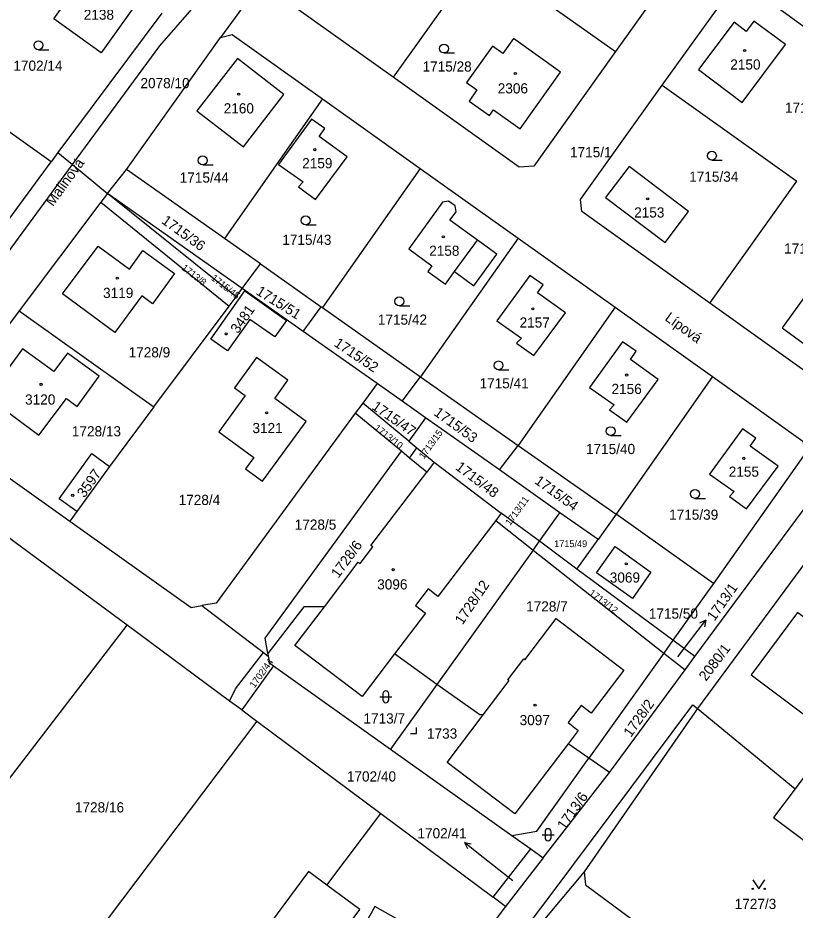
# Model space of a CAD drawing. Extents: x -679220 to -673243, y -1075091 to -1066557.
# Drawn here: x -677014 to -676884, y -1072084.9 to -1071935.7 of the extents above; entities that cross this region are included whole.
import ezdxf

# ---------------------------------------------------------------- set-up
doc = ezdxf.new("R2010")
doc.units = 0
for name, color, linetype in [('Hranice parcel', 7, 'Continuous'), ('Parcelní čísla', 7, 'Continuous'), ('Pop  PČ popisy', 7, 'Continuous'), ('Vnitřní kresba', 7, 'Continuous'), ('Značky budov', 7, 'Continuous'), ('Značky kultur', 7, 'Continuous')]:
    doc.layers.add(name, color=color, linetype=linetype)

msp = doc.modelspace()

# ---------------------------------------------------------------- linework, layer by layer
at = {"layer": 'Hranice parcel'}
for p, q in [((-676901.29, -1071923.42), (-676914.04, -1071941.35)), ((-676936.67, -1071925.2), (-676951.19, -1071945.63)), ((-676936.67, -1071925.2), (-676914.04, -1071941.35)), ((-676972.46, -1071928.53), (-676980.07, -1071938.97)), ((-676906.21, -1071946.96), (-676893.51, -1071929.18)), ((-676893.51, -1071929.18), (-676871.16, -1071945.4)), ((-676989.9, -1071934.91), (-677007.25, -1071958.24)), ((-676995.79, -1071961.08), (-676980.07, -1071938.97)), ((-677008.37, -1071959.75), (-677027, -1071946.58)), ((-676906.21, -1071946.96), (-676883.7, -1071963)), ((-676963.02, -1071949.25), (-676979.39, -1071972.61)), ((-676963.02, -1071949.25), (-676946.71, -1071960.86)), ((-677007.25, -1071958.24), (-677008.37, -1071959.75)), ((-677007.25, -1071958.24), (-677004.82, -1071960.24)), ((-677038.35, -1072005.77), (-677004.82, -1071960.24)), ((-677004.82, -1071960.24), (-676998.96, -1071965.06)), ((-676946.71, -1071960.86), (-676963.04, -1071984.14)), ((-676946.71, -1071960.86), (-676930.33, -1071972.54)), ((-676998.96, -1071965.06), (-676995.79, -1071961.08)), ((-676979.39, -1071972.61), (-676995.79, -1071961.08)), ((-676898.24, -1071983.39), (-676883.7, -1071963)), ((-676998.96, -1071965.06), (-677000.06, -1071966.52)), ((-676976.46, -1071980.95), (-676998.96, -1071965.06)), ((-676977.47, -1071982.31), (-676998.96, -1071965.06)), ((-677000.06, -1071966.52), (-677013.72, -1071984.7)), ((-677000.06, -1071966.52), (-676978.64, -1071983.88)), ((-676973.4, -1071976.84), (-676979.39, -1071972.61)), ((-676930.33, -1071972.54), (-676946.62, -1071995.69)), ((-676930.33, -1071972.54), (-676914.09, -1071984.09)), ((-676976.46, -1071980.95), (-676973.4, -1071976.84)), ((-676973.4, -1071976.84), (-676963.24, -1071983.99)), ((-676977.47, -1071982.31), (-676976.46, -1071980.95)), ((-676966.23, -1071988.15), (-676976.46, -1071980.95)), ((-676978.64, -1071983.88), (-676977.47, -1071982.31)), ((-677013.72, -1071984.7), (-676991.21, -1072000.73)), ((-676991.21, -1072000.73), (-676978.64, -1071983.88)), ((-676966.23, -1071988.15), (-676963.24, -1071983.99)), ((-676963.24, -1071983.99), (-676963.04, -1071984.14)), ((-676963.04, -1071984.14), (-676946.62, -1071995.69)), ((-676914.09, -1071984.09), (-676930.32, -1072007.19)), ((-676914.09, -1071984.09), (-676897.82, -1071995.66)), ((-676953.9, -1071996.85), (-676966.23, -1071988.15)), ((-676949.7, -1071999.8), (-676946.62, -1071995.69)), ((-676946.62, -1071995.69), (-676930.32, -1072007.19)), ((-676897.82, -1071995.66), (-676913.91, -1072018.68)), ((-676953.9, -1071996.85), (-676956.29, -1072000.12)), ((-676949.7, -1071999.8), (-676953.9, -1071996.85)), ((-676991.21, -1072000.73), (-676998.63, -1072010.68)), ((-676956.29, -1072000.12), (-676957.53, -1072001.81)), ((-676948.59, -1072006.45), (-676956.29, -1072000.12)), ((-676945.77, -1072002.57), (-676949.7, -1071999.8)), ((-676949.83, -1072008.14), (-676957.53, -1072001.81)), ((-676945.77, -1072002.57), (-676948.59, -1072006.45)), ((-676933.45, -1072011.27), (-676945.77, -1072002.57)), ((-676948.59, -1072006.45), (-676947.23, -1072007.57)), ((-676948.45, -1072009.28), (-676949.83, -1072008.14)), ((-676948.45, -1072009.28), (-676947.23, -1072007.57)), ((-676947.23, -1072007.57), (-676944.34, -1072009.96)), ((-676933.45, -1072011.27), (-676930.32, -1072007.19)), ((-676930.32, -1072007.19), (-676913.91, -1072018.68)), ((-676945.6, -1072011.62), (-676948.45, -1072009.28)), ((-676944.34, -1072009.96), (-676945.6, -1072011.62)), ((-676944.34, -1072009.96), (-676933.12, -1072018.49)), ((-676998.63, -1072010.68), (-677004.08, -1072018.21)), ((-676923.36, -1072018.44), (-676933.45, -1072011.27)), ((-676900.74, -1072042.46), (-676877.7, -1072011.25)), ((-676873.46, -1072014.72), (-676900.33, -1072051.15)), ((-677004.08, -1072018.21), (-677005.26, -1072019.82)), ((-676933.12, -1072018.49), (-676934.06, -1072019.73)), ((-676926.76, -1072023.2), (-676933.12, -1072018.49)), ((-676926.76, -1072023.2), (-676923.36, -1072018.44)), ((-676916.94, -1072022.92), (-676923.36, -1072018.44)), ((-676913.91, -1072018.68), (-676916.94, -1072022.92)), ((-676897.67, -1072030.26), (-676913.91, -1072018.68)), ((-676934.06, -1072019.73), (-676927.81, -1072024.66)), ((-676995.7, -1072037.23), (-677017.03, -1072021.51)), ((-676927.81, -1072024.66), (-676926.76, -1072023.2)), ((-676920.47, -1072027.86), (-676926.76, -1072023.2)), ((-676920.47, -1072027.86), (-676916.94, -1072022.92)), ((-676927.81, -1072024.66), (-676943.88, -1072047.12)), ((-676927.81, -1072024.66), (-676905.97, -1072041.9)), ((-676904.42, -1072039.73), (-676920.47, -1072027.86)), ((-676897.67, -1072030.26), (-676904.42, -1072039.73)), ((-676983.19, -1072033.95), (-676972.88, -1072041.79)), ((-677028.68, -1072080.19), (-676995.7, -1072037.23)), ((-676978.55, -1072049.91), (-676995.7, -1072037.23)), ((-676904.42, -1072039.73), (-676905.97, -1072041.9)), ((-676900.74, -1072042.46), (-676904.42, -1072039.73)), ((-676972.88, -1072041.79), (-676972.1, -1072042.38)), ((-676972.16, -1072041.94), (-676972.1, -1072042.38)), ((-676943.88, -1072047.12), (-676950.99, -1072042.03)), ((-676905.97, -1072041.9), (-676918.48, -1072059.45)), ((-676905.97, -1072041.9), (-676902.4, -1072044.71)), ((-676902.4, -1072044.71), (-676900.74, -1072042.46)), ((-676971.22, -1072044.03), (-676976.51, -1072051.39)), ((-676971.22, -1072044.03), (-676951.64, -1072057.95)), ((-676943.88, -1072047.12), (-676951.64, -1072057.95)), ((-676976.51, -1072051.39), (-676978.55, -1072049.91)), ((-676976.51, -1072051.39), (-676973.98, -1072053.28)), ((-676900.33, -1072051.15), (-676919.29, -1072078.44)), ((-676900.33, -1072051.15), (-676884, -1072064.55)), ((-676973.98, -1072053.28), (-676953.27, -1072068.7)), ((-676918.48, -1072059.45), (-676921.97, -1072057.07)), ((-676951.64, -1072057.95), (-676931.36, -1072072.37)), ((-676915.01, -1072061.82), (-676918.48, -1072059.45)), ((-676926.11, -1072076.11), (-676915.01, -1072061.82)), ((-676962.32, -1072080.65), (-676953.27, -1072068.7)), ((-676953.27, -1072068.7), (-676934.47, -1072082.69)), ((-676931.36, -1072072.37), (-676928.2, -1072074.62)), ((-676934.47, -1072082.69), (-676928.2, -1072074.62)), ((-676928.2, -1072074.62), (-676926.11, -1072076.11)), ((-676926.11, -1072076.11), (-676932.42, -1072084.22)), ((-676919.29, -1072078.44), (-676927.29, -1072088.05)), ((-676932.42, -1072084.22), (-676934.47, -1072082.69)), ((-676932.42, -1072084.22), (-676965.77, -1072128.57))]:
    msp.add_line(p, q, dxfattribs=at)
for points in [[(-677004.82, -1071960.24), (-676990.19, -1071940.38), (-676962.75, -1071908.83), (-676942.14, -1071882.34), (-676915.32, -1071846.3), (-676903, -1071827.69)], [(-677000.04, -1071941.54), (-677007.96, -1071935.89), (-677002.6, -1071928.37), (-677001.38, -1071929.24), (-677000.07, -1071927.33), (-676993.33, -1071932.13), (-677000.04, -1071941.54)], [(-676951.19, -1071945.63), (-676972.45, -1071930.47), (-676972.46, -1071928.53)], [(-676892.16, -1071937.98), (-676894.19, -1071936.45), (-676900.14, -1071944.35), (-676892.87, -1071949.83), (-676885.6, -1071940.18), (-676890.9, -1071936.24), (-676892.16, -1071937.98)], [(-676980.07, -1071938.97), (-676978.14, -1071938.48), (-676963.02, -1071949.25)], [(-676938.48, -1071949.61), (-676935.11, -1071952.02), (-676934.42, -1071951.06), (-676929.97, -1071954.25), (-676923.2, -1071944.8), (-676931.08, -1071939.16), (-676932.85, -1071941.66), (-676934.58, -1071940.42), (-676938.94, -1071946.51), (-676937.21, -1071947.75), (-676938.48, -1071949.61)], [(-676914.04, -1071941.35), (-676927.67, -1071960.51), (-676930.16, -1071960.64), (-676951.19, -1071945.63)], [(-676977.25, -1071942.49), (-676984.02, -1071951.26), (-676976.24, -1071957.27), (-676969.47, -1071948.5), (-676977.25, -1071942.49)], [(-676898.24, -1071983.39), (-676919.64, -1071968.09), (-676919.87, -1071966.08), (-676906.21, -1071946.96)], [(-676958.9, -1071958.91), (-676963.56, -1071955.56), (-676962.61, -1071954.2), (-676964.84, -1071952.64), (-676970.36, -1071960.24), (-676966.25, -1071963.14), (-676967.05, -1071963.96), (-676964.17, -1071966.06), (-676958.9, -1071958.91)], [(-677063.84, -1071978.51), (-677036.99, -1071997.4), (-677035.86, -1071997.1), (-677008.37, -1071959.75)], [(-676911.75, -1071960.55), (-676915.69, -1071965.74), (-676905.75, -1071973.26), (-676901.84, -1071968.09), (-676911.75, -1071960.55)], [(-676944.73, -1071977.13), (-676945.43, -1071978.09), (-676942.48, -1071980.24), (-676940.94, -1071978.13), (-676937.71, -1071980.48), (-676933.86, -1071975.21), (-676937.09, -1071972.88), (-676941.72, -1071969.55), (-676940.69, -1071968.11), (-676940.83, -1071967.14), (-676941.97, -1071966.35), (-676942.95, -1071966.49), (-676948.6, -1071974.31), (-676944.73, -1071977.13)], [(-677000.55, -1071973.86), (-676995.3, -1071977.69), (-676993.03, -1071974.58), (-676987.75, -1071978.44), (-676991.42, -1071983.5), (-676993.23, -1071982.17), (-676997.73, -1071988.29), (-677006.47, -1071981.86), (-677000.55, -1071973.86)], [(-676926.12, -1071980.31), (-676928.35, -1071978.75), (-676933.87, -1071986.35), (-676929.77, -1071989.25), (-676930.56, -1071990.07), (-676927.68, -1071992.17), (-676922.41, -1071985.02), (-676927.07, -1071981.67), (-676926.12, -1071980.31)], [(-676877.28, -1071993.98), (-676870.29, -1071984.34), (-676879.2, -1071977.88), (-676886.19, -1071987.51), (-676877.28, -1071993.98)], [(-676861.04, -1071979.15), (-676874.99, -1071998.27), (-676877.55, -1071998.21), (-676898.24, -1071983.39)], [(-676981.68, -1071989.39), (-676976.02, -1071981.35), (-676969.05, -1071986.32), (-676971, -1071989.04), (-676975.18, -1071986.11), (-676978.89, -1071991.38), (-676981.68, -1071989.39)], [(-677013.72, -1071984.7), (-677026.18, -1072001.27), (-677025.53, -1072005.41), (-677005.26, -1072019.82)], [(-676906.89, -1071996.14), (-676911.55, -1071992.8), (-676910.6, -1071991.43), (-676912.84, -1071989.87), (-676918.36, -1071997.48), (-676914.25, -1072000.37), (-676915.05, -1072001.2), (-676912.16, -1072003.3), (-676906.89, -1071996.14)], [(-677005.66, -1071991.74), (-677007.93, -1071994.84), (-677013.18, -1071991.02), (-677019.07, -1071999.03), (-677010.45, -1072005.45), (-677005.84, -1071999.31), (-677004.04, -1072000.66), (-677000.38, -1071995.59), (-677005.66, -1071991.74)], [(-676971, -1071999.35), (-676968.79, -1071996.29), (-676974.06, -1071992.48), (-676977.72, -1071997.55), (-676975.97, -1071998.82), (-676980.37, -1072004.9), (-676974.51, -1072009.19), (-676975.88, -1072011.06), (-676973.03, -1072013.17), (-676965.73, -1072003.16), (-676971, -1071999.35)], [(-676897.82, -1071995.66), (-676882.69, -1072006.44), (-676882.34, -1072008.54), (-676897.67, -1072030.26)], [(-676957.53, -1072001.81), (-676980.77, -1072033.56), (-676983.19, -1072033.95)], [(-676891.5, -1072007.3), (-676890.55, -1072005.94), (-676892.79, -1072004.38), (-676898.31, -1072011.98), (-676894.2, -1072014.88), (-676894.99, -1072015.7), (-676892.11, -1072017.8), (-676886.84, -1072010.65), (-676891.5, -1072007.3)], [(-677004.08, -1072018.21), (-677007.03, -1072016.08), (-677001.58, -1072008.55), (-676998.63, -1072010.68)], [(-676972.16, -1072041.94), (-676972.59, -1072039.38), (-676949.83, -1072008.14)], [(-676962.71, -1072034.15), (-676957.03, -1072026.69), (-676956.73, -1072026.91), (-676954.62, -1072024.13), (-676954.93, -1072023.88), (-676945.6, -1072011.62)], [(-677005.26, -1072019.82), (-676984.99, -1072034.24), (-676983.19, -1072033.95)], [(-676934.06, -1072019.73), (-676943.72, -1072032.43), (-676945.37, -1072031.15), (-676947.49, -1072033.94), (-676945.82, -1072035.21), (-676950.99, -1072042.03)], [(-676917.21, -1072028.45), (-676914.09, -1072024.08), (-676908.14, -1072028.37), (-676911.21, -1072032.74), (-676917.21, -1072028.45)], [(-676962.71, -1072034.15), (-676966.11, -1072034.14), (-676972.16, -1072041.94)], [(-676950.99, -1072042.03), (-676956.41, -1072049.16), (-676967.62, -1072040.6), (-676962.71, -1072034.15)], [(-676868.02, -1072077.66), (-676867.08, -1072076.45), (-676872.09, -1072072.31), (-676868.03, -1072066.91), (-676866.12, -1072068.42), (-676863.83, -1072065.54), (-676867.87, -1072061.91), (-676862.44, -1072054.78), (-676858.43, -1072057.77), (-676851.76, -1072049.4), (-676847.29, -1072052.86), (-676843.34, -1072047.64), (-676857.56, -1072036.75), (-676866.88, -1072047.56), (-676883.62, -1072035.08), (-676891.33, -1072045.54), (-676877.52, -1072055.87), (-676884, -1072064.55)], [(-676936.15, -1072052.22), (-676931.81, -1072046.49), (-676932.01, -1072046.34), (-676929.38, -1072042.87), (-676929.17, -1072043.03), (-676923.94, -1072036.13), (-676912.63, -1072044.75), (-676918.09, -1072051.93), (-676919.78, -1072050.64), (-676921.96, -1072053.51), (-676920.25, -1072054.81), (-676921.97, -1072057.07)], [(-676978.55, -1072049.91), (-676977.55, -1072047.85), (-676972.88, -1072041.79)], [(-676972.1, -1072042.38), (-676971.9, -1072043.53), (-676971.22, -1072044.03)], [(-676915.01, -1072061.82), (-676914.7, -1072061.42), (-676902.4, -1072044.71)], [(-676936.15, -1072052.22), (-676936.74, -1072052.23), (-676943.88, -1072047.12)], [(-677003.56, -1072188.05), (-676937.07, -1072098.47), (-676924.77, -1072082.25), (-676901.08, -1072050.53), (-676900.33, -1072051.15)], [(-676973.98, -1072053.28), (-677000.89, -1072088.91), (-677006.95, -1072096.23)], [(-676921.97, -1072057.07), (-676930.86, -1072068.74), (-676942.16, -1072060.15), (-676936.15, -1072052.22)], [(-676931.36, -1072072.37), (-676927.2, -1072071.67), (-676918.48, -1072059.45)], [(-676884, -1072064.55), (-676887.59, -1072069.36), (-676871.15, -1072081.68), (-676868.02, -1072077.66)], [(-676962.32, -1072080.65), (-676965.37, -1072078.39), (-676971.7, -1072086.99), (-676968.77, -1072089.16)], [(-676919.29, -1072078.44), (-676919.07, -1072080.61), (-676880.11, -1072109.47), (-676878.47, -1072110.68)], [(-676968.77, -1072089.16), (-676963.12, -1072093.36), (-676960.03, -1072089.15), (-676957.88, -1072090.71), (-676961.29, -1072096.87), (-676956.26, -1072099.62), (-676957.84, -1072102.51), (-676957.52, -1072102.7), (-676948.9, -1072087.27), (-676954.27, -1072084.27), (-676956.41, -1072088.09), (-676958.21, -1072086.72), (-676956.77, -1072084.77), (-676962.32, -1072080.65)]]:
    msp.add_lwpolyline(points, dxfattribs=at)
at = {"layer": 'Pop  PČ popisy'}
for p, q in [((-676900.76, -1072038.79), (-676898.95, -1072036.39)), ((-676898.95, -1072036.39), (-676899.96, -1072036.89)), ((-676898.95, -1072036.39), (-676899.16, -1072037.49)), ((-676903.61, -1072042.52), (-676900.76, -1072038.79)), ((-676936.92, -1072075.43), (-676939.25, -1072073.54)), ((-676939.25, -1072073.54), (-676938.16, -1072073.78)), ((-676939.25, -1072073.54), (-676938.79, -1072074.56)), ((-676931.22, -1072079.98), (-676936.92, -1072075.43))]:
    msp.add_line(p, q, dxfattribs=at)
at = {"layer": 'Vnitřní kresba'}
msp.add_line((-676940.94, -1071978.13), (-676937.09, -1071972.88), dxfattribs=at)
at = {"layer": 'Značky budov'}
for centre in [(-676892.44, -1071941.17), (-676930.78, -1071945.01), (-676977.04, -1071948.47), (-676964.31, -1071957.74), (-676908.65, -1071965.96), (-676942.82, -1071972.32), (-676997.32, -1071979.22), (-676927.85, -1071984.34), (-676979.13, -1071988.54), (-676912.17, -1071995.41), (-677010.07, -1071996.96), (-676972.36, -1072001.73), (-676892.58, -1072009.33), (-677004.78, -1072015.51), (-676951.2, -1072027.94), (-676912.23, -1072026.98), (-676927.48, -1072050.58)]:
    msp.add_circle(centre, 0.175, dxfattribs=at)
at = {"layer": 'Značky kultur'}
for p, q in [((-677010.5, -1071941.03), (-677008.75, -1071941.03)), ((-676942.71, -1071941.58), (-676940.96, -1071941.58)), ((-676983.04, -1071960.29), (-676981.29, -1071960.29)), ((-676897.92, -1071959.51), (-676896.17, -1071959.51)), ((-676965.83, -1071970.32), (-676964.08, -1071970.32)), ((-676950.17, -1071983.85), (-676948.42, -1071983.85)), ((-676933.59, -1071994.56), (-676931.84, -1071994.56)), ((-676914.84, -1072005.54), (-676913.09, -1072005.54)), ((-676900.74, -1072016.02), (-676898.99, -1072016.02)), ((-676952.93, -1072048.69), (-676952.93, -1072049.69)), ((-676951.93, -1072049.69), (-676951.93, -1072048.69)), ((-676953.43, -1072049.19), (-676951.43, -1072049.19)), ((-676947.3, -1072055.33), (-676947.3, -1072054.33)), ((-676948.3, -1072055.33), (-676947.3, -1072055.33)), ((-676926.31, -1072072.24), (-676924.31, -1072072.24)), ((-676925.81, -1072071.74), (-676925.81, -1072072.74)), ((-676924.81, -1072072.74), (-676924.81, -1072071.74))]:
    msp.add_line(p, q, dxfattribs=at)
msp.add_lwpolyline([(-676891.09, -1072079.79), (-676890.09, -1072081.29), (-676889.09, -1072079.79)], dxfattribs=at)
for centre, radius in [((-677010.5, -1071940.28), 0.75), ((-676942.71, -1071940.83), 0.75), ((-676983.04, -1071959.54), 0.75), ((-676897.92, -1071958.76), 0.75), ((-676965.83, -1071969.57), 0.75), ((-676950.17, -1071983.1), 0.75), ((-676933.59, -1071993.81), 0.75), ((-676914.84, -1072004.79), 0.75), ((-676900.74, -1072015.27), 0.75), ((-676891.09, -1072081.29), 0.1), ((-676889.09, -1072081.29), 0.1)]:
    msp.add_circle(centre, radius, dxfattribs=at)
for centre, start, end in [((-676952.43, -1072048.69), 0, 180), ((-676952.43, -1072049.69), 180, 359.9879), ((-676925.31, -1072071.74), 0, 180), ((-676925.31, -1072072.74), 180, 359.9879)]:
    msp.add_arc(centre, 0.5, start, end, dxfattribs=at)

# ---------------------------------------------------------------- texts
at = {"layer": 'Parcelní čísla'}
for s, height, p in [('2138', 1.7, (-677002.93, -1071936.02)), ('1702/14', 1.7, (-677014.7, -1071944.55)), ('1715/28', 1.7, (-676946.29, -1071944.69)), ('2150', 1.7, (-676894.84, -1071944.35)), ('2078/10', 1.7, (-676993.45, -1071947.46)), ('2306', 1.7, (-676933.72, -1071948.34)), ('2160', 1.7, (-676979.54, -1071951.68)), ('1715/31', 1.7, (-676885.7, -1071951.57)), ('1715/1', 1.7, (-676921.64, -1071959.01)), ('2159', 1.7, (-676966.41, -1071960.85)), ('1715/44', 1.7, (-676986.89, -1071963.25)), ('1715/34', 1.7, (-676901.71, -1071963.1)), ('2153', 1.7, (-676910.91, -1071969.08)), ('1715/43', 1.7, (-676969.74, -1071973.65)), ('2158', 1.7, (-676945.18, -1071975.48)), ('1715/35', 1.7, (-676885.84, -1071975.11)), ('3119', 1.7, (-676999.7, -1071982.53)), ('1715/42', 1.7, (-676953.76, -1071987)), ('2157', 1.7, (-676930.07, -1071987.48)), ('1728/9', 1.7, (-676995.43, -1071992.46)), ('1715/41', 1.7, (-676936.76, -1071997.64)), ('2156', 1.7, (-676914.7, -1071998.58)), ('3120', 1.7, (-677012.74, -1072000.35)), ('1728/13', 1.7, (-677004.92, -1072005.66)), ('3121', 1.7, (-676974.73, -1072005.12)), ('1715/40', 1.7, (-676918.97, -1072008.62)), ('2155', 1.7, (-676895.1, -1072012.41)), ('1728/4', 1.7, (-676987.07, -1072017.13)), ('1715/39', 1.7, (-676905.07, -1072019.6)), ('1728/5', 1.7, (-676967.66, -1072021.26)), ('1715/49', 1.14, (-676924.28, -1072024.18)), ('3096', 1.7, (-676953.87, -1072031.25)), ('3069', 1.7, (-676914.99, -1072030.1)), ('1728/7', 1.7, (-676928.97, -1072034.93)), ('1715/50', 1.7, (-676908.46, -1072036.13)), ('1713/7', 1.7, (-676956.17, -1072053.66)), ('3097', 1.7, (-676930.06, -1072053.93)), ('1733', 1.7, (-676945.55, -1072056.18)), ('1702/40', 1.7, (-676958.94, -1072063.35)), ('1728/16', 1.7, (-677004.41, -1072068.52)), ('1702/41', 1.7, (-676947.14, -1072072.85)), ('1727/3', 1.7, (-676894.11, -1072084.66))]:
    msp.add_text(s, height=height, dxfattribs=at).set_placement(p)
for s, height, rotation, p in [('1715/36', 1.7, 324, (-676990.05, -1071969.93)), ('1713/8', 1.14, 322, (-676986.67, -1071977.69)), ('1715/45', 1.14, 322, (-676981.73, -1071979.4)), ('1715/51', 1.7, 328, (-676974.26, -1071981.83)), ('3481', 1.7, 55, (-676977.15, -1071988.6)), ('1715/52', 1.7, 326, (-676961.22, -1071990.46)), ('1715/47', 1.7, 325, (-676954.91, -1072001)), ('1715/53', 1.7, 324, (-676944.53, -1072002.01)), ('1713/10', 1.14, 322, (-676954.47, -1072004.46)), ('1713/15', 1.14, 54, (-676946.08, -1072009.54)), ('1715/48', 1.7, 323, (-676940.92, -1072011.08)), ('3597', 1.7, 55, (-677002.81, -1072016.04)), ('1715/54', 1.7, 324, (-676927.69, -1072013.41)), ('1713/11', 1.14, 54, (-676931.65, -1072020.66)), ('1728/6', 1.7, 54, (-676960.36, -1072029.47)), ('1728/12', 1.7, 56, (-676939.61, -1072037.27)), ('1713/1', 1.7, 55, (-676897.49, -1072036.65)), ('1713/12', 1.14, 323, (-676918.57, -1072032.05)), ('2080/1', 1.7, 53, (-676898.89, -1072046.69)), ('1702/44', 1.14, 54, (-676974.39, -1072047.81)), ('1728/2', 1.7, 55, (-676911.45, -1072056.07)), ('1713/6', 1.7, 55, (-676922.53, -1072071.57))]:
    msp.add_text(s, height=height, rotation=rotation, dxfattribs=at).set_placement(p)
at = {"layer": 'Pop  PČ popisy'}
for s, rotation, p in [('Malinová', 54, (-677008.09, -1071967.33)), ('Lípová', 324, (-676905.9, -1071986.16))]:
    msp.add_text(s, height=1.7, rotation=rotation, dxfattribs=at).set_placement(p)

doc.saveas('drawing.dxf')
